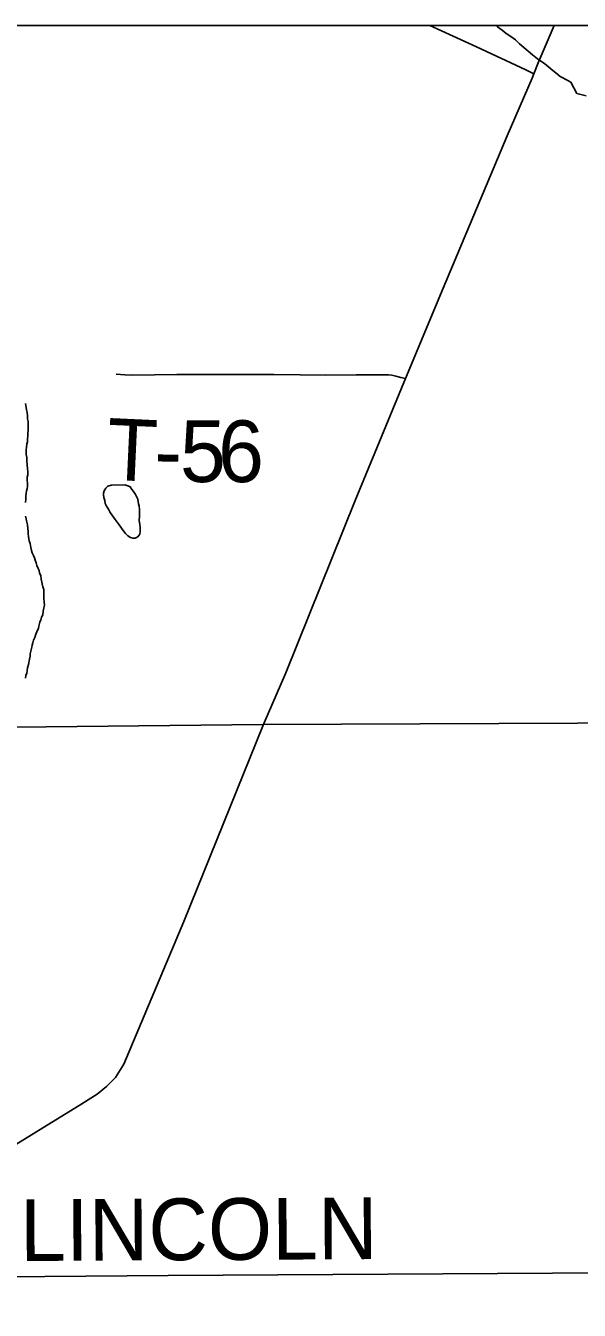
# Model space of a CAD drawing. Extents: x 0 to 34, y 0 to 22.
# Drawn here: x 5.693 to 6.203, y 19.717 to 20.9 of the extents above; entities that cross this region are included whole.
import ezdxf

# ---------------------------------------------------------------- set-up
doc = ezdxf.new("R2010")
doc.units = 0
for name, color, linetype in [('GM_X_Corporation', 7, 'Continuous'), ('GM_X_Major_River', 7, 'Continuous'), ('GM_X_Minor_Lake', 7, 'Continuous'), ('GM_X_Minor_River', 7, 'Continuous'), ('GM_X_State_Route', 7, 'Continuous'), ('GM_X_Township_Road', 7, 'Continuous'), ('GM_X_Township_Road_Text', 7, 'Continuous'), ('SH_Data', 7, 'Continuous')]:
    doc.layers.add(name, color=color, linetype=linetype)

msp = doc.modelspace()

# ---------------------------------------------------------------- linework, layer by layer
at = {"layer": 'GM_X_Corporation'}
for points in [[(7.8853, 20.9), (2.1, 20.9)], [(7.8853, 20.9), (2.6713, 20.9)], [(6.8535, 20.2607), (5.9115, 20.2566), (4.9416, 20.2461), (4.2353, 20.2419)], [(4.2353, 20.2419), (4.9416, 20.2461), (5.9115, 20.2566), (6.8535, 20.2607)], [(6.8535, 20.2607), (5.9115, 20.2566), (4.9416, 20.2461), (4.2353, 20.2419)], [(4.2353, 20.2419), (4.9416, 20.2461), (5.9115, 20.2566), (6.8535, 20.2607)]]:
    msp.add_lwpolyline(points, dxfattribs=at)
at = {"layer": 'GM_X_Major_River'}
for points in [[(5.6942, 20.515), (5.6946, 20.5169), (5.6946, 20.5192), (5.6949, 20.5223), (5.6949, 20.5249), (5.6953, 20.5276), (5.6952, 20.5303), (5.6952, 20.5325), (5.6952, 20.5356), (5.6948, 20.5379), (5.6947, 20.5409), (5.6943, 20.5439), (5.6939, 20.5462), (5.6935, 20.5485), (5.6931, 20.5504), (5.6927, 20.5523)], [(5.6929, 20.461), (5.6932, 20.464), (5.6932, 20.4671), (5.6936, 20.4694), (5.6939, 20.4716), (5.6943, 20.4739), (5.6946, 20.4758), (5.6945, 20.4842), (5.6949, 20.4865), (5.6949, 20.4892), (5.6948, 20.4922), (5.6944, 20.4956), (5.694, 20.4994), (5.694, 20.5025), (5.6936, 20.5051), (5.6936, 20.5078), (5.6935, 20.5097), (5.6939, 20.5116), (5.6942, 20.515)], [(5.693, 20.2992), (5.6933, 20.3019), (5.6941, 20.3038), (5.6948, 20.3088), (5.6955, 20.3118), (5.6966, 20.3168), (5.697, 20.3195), (5.6973, 20.3217), (5.6988, 20.3279), (5.6991, 20.3298), (5.6995, 20.3317), (5.7002, 20.3343), (5.7013, 20.3366), (5.7025, 20.3397), (5.7032, 20.342), (5.7047, 20.3454), (5.705, 20.3473), (5.7061, 20.3508), (5.7069, 20.3531), (5.7076, 20.3553), (5.7087, 20.3576), (5.7091, 20.3611), (5.7098, 20.3641), (5.7102, 20.3664), (5.7101, 20.3694), (5.7097, 20.3729), (5.7097, 20.3748), (5.7097, 20.3782), (5.7096, 20.3809), (5.7089, 20.3835), (5.7073, 20.3903), (5.7069, 20.3934), (5.7057, 20.3964), (5.7053, 20.3983), (5.7045, 20.4002), (5.7033, 20.4029), (5.7026, 20.4055), (5.7018, 20.4078), (5.701, 20.4101), (5.7002, 20.4123), (5.699, 20.4146), (5.6983, 20.4169), (5.6979, 20.4195), (5.6971, 20.4233), (5.6963, 20.4256), (5.6959, 20.4275), (5.6955, 20.4298), (5.6954, 20.4321), (5.6954, 20.4344), (5.695, 20.437), (5.6946, 20.4404), (5.6938, 20.4442), (5.6934, 20.4461), (5.693, 20.4484)]]:
    msp.add_lwpolyline(points, dxfattribs=at)
at = {"layer": 'GM_X_Minor_Lake'}
for points in [[(5.7725, 20.477), (5.7718, 20.477), (5.7688, 20.4762), (5.7669, 20.4743), (5.7654, 20.4716), (5.7646, 20.4697), (5.7647, 20.4678), (5.7651, 20.4655), (5.7658, 20.4629), (5.7663, 20.4602), (5.7674, 20.4576), (5.7693, 20.4549), (5.7709, 20.4519)], [(5.7709, 20.4519), (5.7755, 20.4455), (5.7774, 20.4428), (5.779, 20.4406), (5.7828, 20.4353), (5.7848, 20.4326), (5.7871, 20.4304), (5.7897, 20.4289), (5.7917, 20.4281), (5.7939, 20.4282), (5.7962, 20.4293), (5.7981, 20.432), (5.7984, 20.4343), (5.7984, 20.4362), (5.7984, 20.4381), (5.798, 20.4411), (5.7976, 20.4442), (5.7979, 20.4488), (5.7979, 20.451), (5.7979, 20.4545), (5.7974, 20.4575), (5.797, 20.4598), (5.7962, 20.464), (5.7955, 20.4659), (5.7943, 20.4685), (5.7924, 20.4711), (5.7908, 20.473), (5.7893, 20.4753), (5.787, 20.4764), (5.7843, 20.4772), (5.7725, 20.477)]]:
    msp.add_lwpolyline(points, dxfattribs=at)
at = {"layer": 'GM_X_Minor_River'}
for points in [[(6.1262, 20.9), (6.1275, 20.8989), (6.1318, 20.8959), (6.1356, 20.8929), (6.1398, 20.8899), (6.144, 20.8869), (6.1478, 20.8832), (6.1517, 20.8798), (6.1559, 20.8764), (6.1597, 20.873), (6.1643, 20.8693), (6.1712, 20.8648), (6.1731, 20.8633), (6.1766, 20.8603), (6.1785, 20.8588), (6.1812, 20.8565), (6.1854, 20.8531), (6.1877, 20.852), (6.1904, 20.8505), (6.1923, 20.8494), (6.1946, 20.8483), (6.195, 20.8479), (6.2005, 20.8374)], [(6.2092, 20.8355), (6.2005, 20.8374)]]:
    msp.add_lwpolyline(points, dxfattribs=at)
at = {"layer": 'GM_X_State_Route'}
for points in [[(5.9117, 20.256), (5.9327, 20.3041), (5.9965, 20.4628), (6.039, 20.5664), (6.0427, 20.5752), (6.0774, 20.6582), (6.1364, 20.7986), (6.1594, 20.8515), (6.1611, 20.8555), (6.1651, 20.8659), (6.1796, 20.9)], [(5.3789, 19.6842), (5.4403, 19.722), (5.4828, 19.7467), (5.5315, 19.7774), (5.6638, 19.8577), (5.7447, 19.9073), (5.7588, 19.9163), (5.7675, 19.9235), (5.7757, 19.9318), (5.7833, 19.9438), (5.8387, 20.0752), (5.9117, 20.256)]]:
    msp.add_lwpolyline(points, dxfattribs=at)
at = {"layer": 'GM_X_Township_Road'}
for points in [[(6.0651, 20.9), (6.1083, 20.8805), (6.1536, 20.8592), (6.1611, 20.8555)], [(5.7765, 20.5793), (5.7842, 20.5785), (5.7911, 20.5782), (5.8321, 20.5789), (5.8849, 20.5789), (5.9216, 20.5787), (5.9458, 20.5784), (5.9688, 20.5782), (5.9974, 20.5784), (6.0217, 20.5786), (6.0272, 20.5784), (6.0301, 20.5781), (6.0339, 20.5773), (6.0384, 20.5762), (6.0427, 20.5752)], [(5.4828, 19.7467), (5.8242, 19.7493), (6.1782, 19.7516), (6.5603, 19.7545)]]:
    msp.add_lwpolyline(points, dxfattribs=at)
at = {"layer": 'SH_Data'}
msp.add_line((2.1, 20.9), (8.9, 20.9), dxfattribs=at)

# ---------------------------------------------------------------- texts
at = {"layer": 'GM_X_Township_Road_Text'}
for s, height, rotation, p in [('T', 0.0568, 357.3593, (5.7666, 20.4821)), ('5', 0.0568, 359.8912, (5.8351, 20.4799)), ('6', 0.0568, 359.9932, (5.8702, 20.4798)), ('-', 0.0568, 359.5975, (5.8114, 20.4801)), ('LINCOLN', 0.05682, 0.3124, (5.6879, 19.7627))]:
    msp.add_text(s, height=height, rotation=rotation, dxfattribs=at).set_placement(p)

doc.saveas('drawing.dxf')
